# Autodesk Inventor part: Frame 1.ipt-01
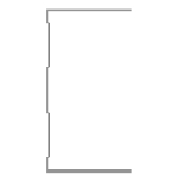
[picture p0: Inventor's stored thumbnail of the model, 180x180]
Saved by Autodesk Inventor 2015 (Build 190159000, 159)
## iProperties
_CCFamilyMember: 1
_CCFamilyDisplayName: Kévin - Kévin Novo
_FrameMemberDoc: Frame Member File
_Version: 15.0.0
_GetPNFromCC: 1
Created: 2015-04
Part Number: Frame 1.ipt-01
Material: Aluminum 6061
Description: Kévin Novo
Document SubType Name: Modeling
Standard: Kevin
Designer: suporte
Standards Organization: Kevin
Language: en-US
Size Designation: (Unnamed 1)
Categories: <MemberInstance><Categories><Category DisplayName="Structural Shapes" InternalName="089c4875-fa83-4c05-b084-43b9cc11f5ed" Mnemonic="GRDR"><CategoryParameter Dis
Density: 2.7 g/cm^3
Appearance: Aluminum - Flat
IsCustomPart: 1
G_L: 1750,000 mm
G_W: 50,000 mm
G_H: 75,000 mm
+654C26D0-0660-45B6-B070-DFA59518F827+CUTDETAIL1: Cut
+16CC4A0E-5CDF-4022-B765-1B915BD698D5+CUTDETAIL2: Cut
Author: suporte
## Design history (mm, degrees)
node "Start Plane"
node "End Plane"
sketch "Sketch"
  geometry: L1 (24.7, 37.5)-(24.7, 36.9); L2 (24.7, 36.9)-(-24.7, 36.9); L3 (-24.7, -36.9)-(24.7, -36.9); L4 (24.7, -36.9)-(24.7, -37.5); L5 (24.7, -37.5)-(-25.3, -37.5); L6 (-25.3, 37.5)-(24.7, 37.5); L7 (-24.7, 36.9)-(-24.7, 31.9); L8 (-24.7, 31.9)-(-23.3, 30.5); L9 (-23.3, 30.5)-(-23.3, 10.934); L10 (-23.3, 10.934)-(-24.7, 9.534); L11 (-24.7, 9.534)-(-24.7, -9.534); L12 (-24.7, -9.534)-(-23.3, -10.934); L13 (-23.3, -10.934)-(-23.3, -30.5); L14 (-23.3, -30.5)-(-24.7, -31.9); L15 (-24.7, -31.9)-(-24.7, -36.9); L16 (-25.3, -37.5)-(-25.3, -31.651); L17 (-25.3, -31.651)-(-23.9, -30.251); L18 (-23.9, -30.251)-(-23.9, -11.183); L19 (-23.9, -11.183)-(-25.3, -9.783); L20 (-25.3, -9.783)-(-25.3, 9.783); L21 (-25.3, 9.783)-(-23.9, 11.183); L22 (-23.9, 11.183)-(-23.9, 30.251); L23 (-23.9, 30.251)-(-25.3, 31.651); L24 (-25.3, 31.651)-(-25.3, 37.5); L25 (-25.3, 0)-(30.37, 0); 3 further points
  constraints: 50 end point, 10 point on line, 9 parallel, 5 perpendicular, 4 equal length, 3 midpoint, 3 vertical, 2 vertical alignment, 1 collinear, 1 horizontal, 1 horizontal alignment
  dimensions: "d3" = 0.6 distance of L1.start L1.end (= d6); "d5" = 75 distance between parallel lines of L5 L6; "d6" = 0.6 distance between parallel lines of L24 L7 (= d8); "d7" = 0.6 distance between parallel lines of L8 L23 (= d8); "d8" = 0.6 distance between parallel lines of L22 L9 (= d12); "Espessura" = 0.6 distance between parallel lines of L17 L14; "d10" = 0.6 distance between parallel lines of L13 L18 (= Espessura); "d11" = 0.6 distance between parallel lines of L12 L19 (= Espessura); "d12" = 0.6 distance between parallel lines of L21 L10 (= d11); "d13" = 5 distance of L2.end L7.end; "d15" = 135 deg angle of L9 L8; "d16" = 2 distance between parallel lines of L24 L9; "d17" = 50 distance of L6.start L1.start
extrude "Body" join sketch "Sketch" stored distance "d24" = 0.13; taper "d25" = 0 deg
node "Driven Length"
  sketch "Sketch10"
    geometry: L1 (0, 0)-(10, 0) reference
    constraints: 2 end point, 1 horizontal
  workplane "Work Plane7"
  sketch "Sketch11"
    geometry: L1 (-2, 25)-(12, 25) reference; L2 (-2, 1775)-(12, 1775) reference
    dimensions: "d27" = 1750 distance between parallel lines of L1 L2 (derived)
workplane "Work Plane8"
split "Split1"
workplane "Work Plane9"
split "Split2"
body "Solid1"
other parameters: "G_OFFSET_START" = -25 [user parameter; used in 1 equation term], "G_OFFSET_END" = -25 [user parameter; used in 1 equation term], "d22" = 25 (= -G_OFFSET_START), "d23" = 1775 (= tamanho + G_OFFSET_END), "G_L" = 1750 (= d27) [user parameter], "d34" = 90 deg
